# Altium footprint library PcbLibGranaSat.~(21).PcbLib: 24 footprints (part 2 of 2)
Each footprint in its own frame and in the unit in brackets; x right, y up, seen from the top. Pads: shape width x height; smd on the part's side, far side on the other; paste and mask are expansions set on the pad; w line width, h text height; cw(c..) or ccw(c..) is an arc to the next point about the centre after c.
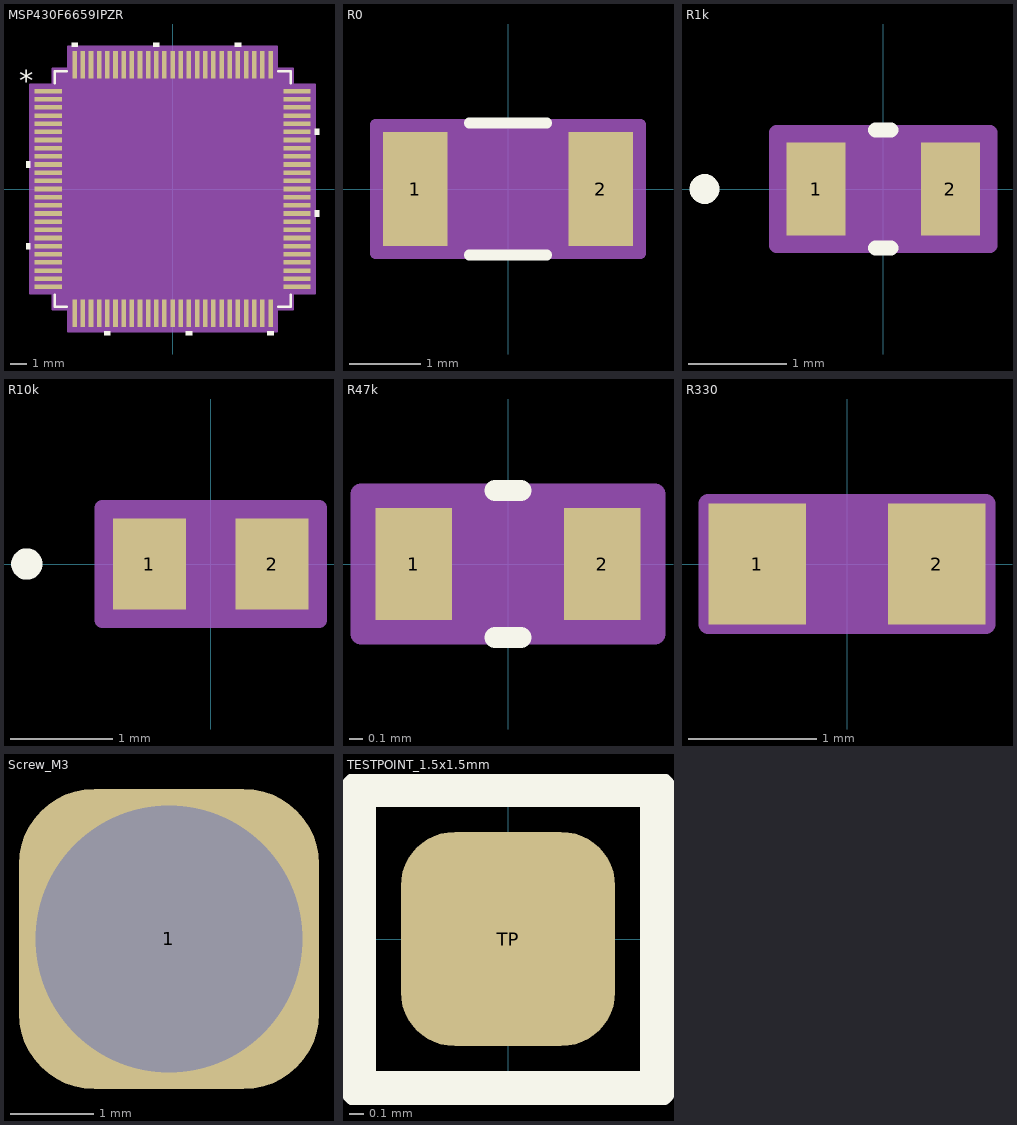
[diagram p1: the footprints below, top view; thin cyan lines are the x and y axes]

## MSP430F6659IPZR [mil]
pads (100):
  rect 66x11 smd paste+0 mask+0: 1(-300,236.22) 2(-300,216.54) 3(-300,196.85) 4(-300,177.17) 5(-300,157.48) 6(-300,137.8) 7(-300,118.11) 8(-300,98.43) 9(-300,78.74) 10(-300,59.06) 11(-300,39.37) 12(-300,19.69) 13(-300,0) 14(-300,-19.68) 15(-300,-39.37) 16(-300,-59.06) 17(-300,-78.74) 18(-300,-98.43) 19(-300,-118.11) 20(-300,-137.8) 21(-300,-157.48) 22(-300,-177.17) 23(-300,-196.85) 24(-300,-216.54) 25(-300,-236.22) 51(300,-236.22) 52(300,-216.54) 53(300,-196.85) 54(300,-177.17) 55(300,-157.48) 56(300,-137.8) 57(300,-118.11) 58(300,-98.43) 59(300,-78.74) 60(300,-59.06) 61(300,-39.37) 62(300,-19.68) 63(300,0) 64(300,19.68) 65(300,39.37) 66(300,59.06) 67(300,78.74) 68(300,98.43) 69(300,118.11) 70(300,137.8) 71(300,157.48) 72(300,177.17) 73(300,196.85) 74(300,216.54) 75(300,236.22)
  rect 11x66 smd paste+0 mask+0: 26(-236.22,-300) 27(-216.54,-300) 28(-196.85,-300) 29(-177.17,-300) 30(-157.48,-300) 31(-137.8,-300) 32(-118.11,-300) 33(-98.43,-300) 34(-78.74,-300) 35(-59.06,-300) 36(-39.37,-300) 37(-19.68,-300) 38(0,-300) 39(19.68,-300) 40(39.37,-300) 41(59.06,-300) 42(78.74,-300) 43(98.43,-300) 44(118.11,-300) 45(137.8,-300) 46(157.48,-300) 47(177.17,-300) 48(196.85,-300) 49(216.54,-300) 50(236.22,-300) 76(236.22,300) 77(216.54,300) 78(196.85,300) 79(177.17,300) 80(157.48,300) 81(137.8,300) 82(118.11,300) 83(98.43,300) 84(78.74,300) 85(59.06,300) 86(39.37,300) 87(19.68,300) 88(0,300) 89(-19.68,300) 90(-39.37,300) 91(-59.06,300) 92(-78.74,300) 93(-98.43,300) 94(-118.11,300) 95(-137.8,300) 96(-157.48,300) 97(-177.17,300) 98(-196.85,300) 99(-216.54,300) 100(-236.22,300)
Top Overlay:
  region: -343,66.56 -353,66.56 -353,51.56 -343,51.56
  region: -343,-130.3 -353,-130.3 -353,-145.3 -343,-145.3
  region: -149.98,-343 -164.98,-343 -164.98,-353 -149.98,-353
  region: 46.87,-343 31.87,-343 31.87,-353 46.87,-353
  region: 243.72,-343 228.72,-343 228.72,-353 243.72,-353
  region: 343,-51.56 353,-51.56 353,-66.56 343,-66.56
  region: 343,145.3 353,145.3 353,130.3 343,130.3
  region: 164.98,343 149.98,343 149.98,353 164.98,353
  region: -31.87,343 -46.87,343 -46.87,353 -31.87,353
  region: -228.72,343 -243.72,343 -243.72,353 -228.72,353
  lines w6: -284.5,-254.82 -284.5,-284.5 -254.82,-284.5 ; -284.5,254.82 -284.5,284.5 -254.82,284.5 ; 254.82,-284.5 284.5,-284.5 284.5,-254.82 ; 254.82,284.5 284.5,284.5 284.5,254.82
  text "*" at -370.5,236.06 h50
Mechanical 13:
  drawing of 405 lines, arcs and shapes, not listed
  text "*" at -277,221.06 h50
Mechanical 15:
  region: -251.72,-289.5 -289.5,-289.5 -289.5,-251.72 -343,-251.72 -343,251.72 -289.5,251.72 -289.5,289.5 -251.72,289.5 -251.72,343 251.72,343 251.72,289.5 289.5,289.5 289.5,251.72 343,251.72 343,-251.72 289.5,-251.72 289.5,-289.5 251.72,-289.5 251.72,-343 -251.72,-343
  lines w6: -343,-251.72 -289.5,-251.72 -289.5,-289.5 -251.72,-289.5 -251.72,-343 251.72,-343 251.72,-289.5 289.5,-289.5 289.5,-251.72 343,-251.72 343,251.72 289.5,251.72 289.5,289.5 251.72,289.5 251.72,343 -251.72,343 -251.72,289.5 -289.5,289.5 -289.5,251.72 -343,251.72 -343,-251.72
3D body: height 10, standoff 0, extent 0,0 10,10
3D body "PZ100.stp": height 63.11, standoff 0, extent -318.03,-319.02 320,319.02

## R0 [mm]
pads (2):
  rect 0.902x1.6 smd paste+0 mask+0: 1(-1.301,0) 2(1.301,0)
Top Overlay:
  lines w0.152: -0.542,-0.927 0.542,-0.927 ; -0.542,0.927 0.542,0.927
Mechanical 13:
  lines w0.025: -1.6,-0.8 -1.6,0.8 ; -1.6,-0.8 1.6,-0.8 ; -1.6,-0.8 -0.85,-0.8 -0.85,0.8 -1.6,0.8 ; -1.6,-0.8 -1.6,0.8 ; -1.6,0.8 1.6,0.8 ; 1.6,-0.8 1.6,0.8 ; 1.6,-0.8 1.6,0.8 ; 1.6,-0.8 0.85,-0.8 0.85,0.8 1.6,0.8
Mechanical 15:
  region: 1.854,-0.902 -1.854,-0.902 -1.854,0.902 1.854,0.902
  lines w0.152: -1.854,-0.902 1.854,-0.902 1.854,0.902 -1.854,0.902 -1.854,-0.902
3D body: height 0.25, standoff 0, extent 0,0 0.254,0.254
3D body "RC1206N-L.stp": height 0.71, standoff 0, extent -1.6,-0.8 1.6,0.8

## R1k [mil]
pads (2):
  rect 23.68x37.4 smd paste+0 mask+0: 1(-27,0) 2(27,0)
Top Overlay:
  circle w6: c-71.84,0 r3
  lines w6: -3.05,-23.7 3.05,-23.7 ; -3.05,23.7 3.05,23.7
Mechanical 13:
  circle w0: c-22,0 r3
  lines w1: -34.84,-18.7 -34.84,18.7 ; -34.84,-18.7 34.84,-18.7 ; -34.84,-18.7 -15.16,-18.7 -15.16,18.7 -34.84,18.7 ; -34.84,-18.7 -34.84,18.7 ; -34.84,18.7 34.84,18.7 ; 34.84,-18.7 34.84,18.7 ; 34.84,-18.7 34.84,18.7 ; 34.84,-18.7 15.16,-18.7 15.16,18.7 34.84,18.7
Mechanical 15:
  region: 42.84,-22.7 -42.84,-22.7 -42.84,22.7 42.84,22.7
  lines w6: -42.84,-22.7 42.84,-22.7 42.84,22.7 -42.84,22.7 -42.84,-22.7
3D body: height 10, standoff 0, extent 0,0 10,10
3D body "0603-L.stp": height 32.99, standoff 0, extent -34.84,-18.7 34.84,18.7

## R10k [mil]
pads (2):
  rect 28x35 smd paste+0 mask+0: 1(-23.5,0) 2(23.5,0)
Top Overlay:
  circle w6: c-70.5,0 r3
Mechanical 13:
  circle w0: c-18.5,0 r3
  lines w1: -33.5,-17.5 -33.5,17.5 ; -33.5,-17.5 33.5,-17.5 ; -33.5,-17.5 -9.5,-17.5 -9.5,17.5 -33.5,17.5 ; -33.5,-17.5 -33.5,17.5 ; -33.5,17.5 33.5,17.5 ; 33.5,-17.5 33.5,17.5 ; 33.5,-17.5 33.5,17.5 ; 33.5,-17.5 9.5,-17.5 9.5,17.5 33.5,17.5
Mechanical 15:
  region: 41.5,-21.5 -41.5,-21.5 -41.5,21.5 41.5,21.5
  lines w6: -41.5,-21.5 41.5,-21.5 41.5,21.5 -41.5,21.5 -41.5,-21.5
3D body: height 10, standoff 0, extent 0,0 10,10
3D body "STA_RNCP0603-L.stp": height 24.02, standoff 0, extent -33.5,-17.48 33.51,17.48

## R47k [mm]
pads (2):
  rect 0.552x0.8 smd paste+0 mask+0: 1(-0.676,0) 2(0.676,0)
Top Overlay:
  lines w0.152: -0.092,-0.527 0.092,-0.527 ; -0.092,0.527 0.092,0.527
Mechanical 13:
  lines w0.025: -0.8,-0.4 -0.8,0.4 ; -0.8,-0.4 0.8,-0.4 ; -0.8,-0.4 -0.4,-0.4 -0.4,0.4 -0.8,0.4 ; -0.8,-0.4 -0.8,0.4 ; -0.8,0.4 0.8,0.4 ; 0.8,-0.4 0.8,0.4 ; 0.8,-0.4 0.8,0.4 ; 0.8,-0.4 0.4,-0.4 0.4,0.4 0.8,0.4
Mechanical 15:
  region: 1.054,-0.502 -1.054,-0.502 -1.054,0.502 1.054,0.502
  lines w0.152: -1.054,-0.502 1.054,-0.502 1.054,0.502 -1.054,0.502 -1.054,-0.502
3D body "RC0603N-L.stp": height 0.71, standoff 0, extent -0.8,-0.4 0.8,0.4
3D body: height 0.25, standoff 0, extent 0,0 0.254,0.254

## R330 [mil]
pads (2):
  rect 30x37 smd paste+0 mask+0: 1(-27.5,0) 2(27.5,0)
Mechanical 13:
  lines w1: -32.5,-18.5 32.5,-18.5 32.5,18.5 -32.5,18.5 -32.5,-18.5
Mechanical 15:
  region: -32.5,-18.5 -42.5,-18.5 -42.5,18.5 -32.5,18.5 32.5,18.5 42.5,18.5 42.5,-18.5 32.5,-18.5
  lines w6: -42.5,-18.5 -42.5,18.5 -32.5,18.5 32.5,18.5 42.5,18.5 42.5,-18.5 32.5,-18.5 -32.5,-18.5 -42.5,-18.5
3D body: height 10, standoff 0, extent 0,0 10,10
3D body "RES_CRCW_0603-L.stp": height 20, standoff 0, extent -32.52,-18.5 32.52,18.51
3D body "RES_CRCW_0603-L.stp": height 20, standoff 0, extent -57.52,-158.5 7.52,-121.49

## Screw_M3 [mm] "Main CubeSAT bus M3 screw"
pads (1):
  rrect50% 3.6x3.6 hole 3.2: 1(72.04,27.44)

## TESTPOINT_1.5x1.5mm [mm] "Punto de test de 1.5x1.5mm"
pads (1):
  rrect50% 1.5x1.5 smd: TP(0,0)
Top Overlay:
  lines w0.254: -1.05,-1.05 1.05,-1.05 1.05,1.05 -1.05,1.05 -1.05,-1.05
